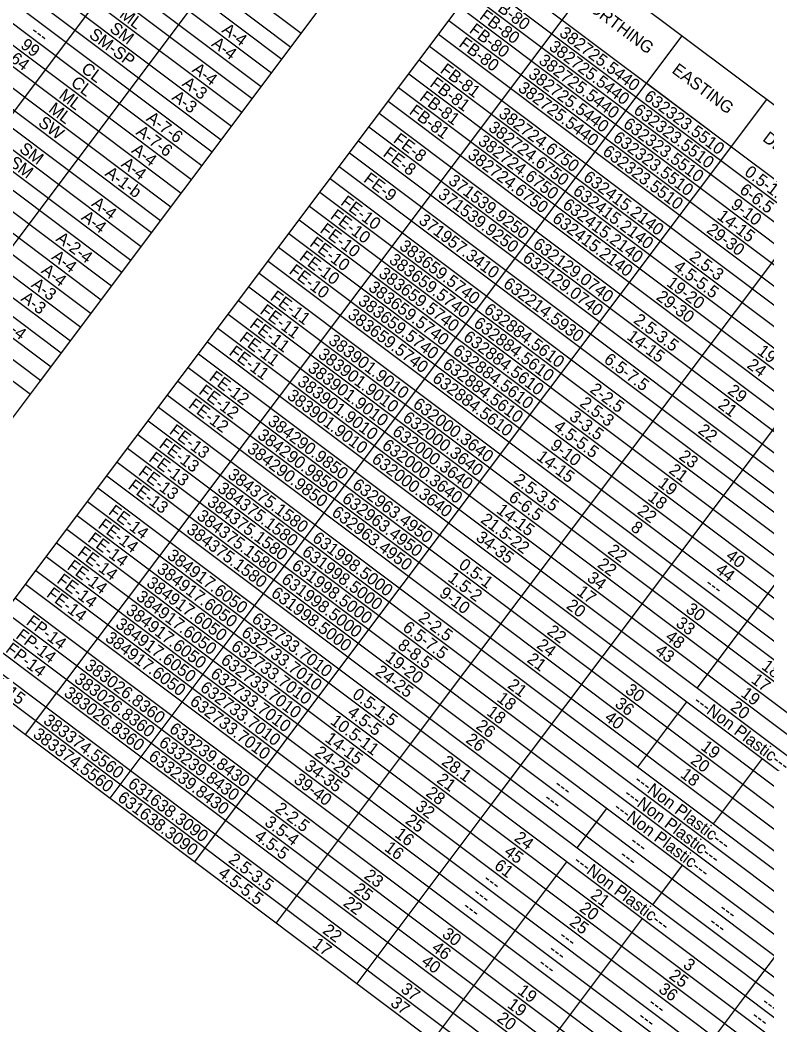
# Model space of a CAD drawing. Extents: x 627484.2 to 627514.4, y 367972.1 to 367996.9.
# Drawn here: x 627490.816 to 627494.205, y 367987.65 to 367992.209 of the extents above; entities that cross this region are included whole.
import ezdxf

# ---------------------------------------------------------------- set-up
doc = ezdxf.new("R2010")
doc.units = 0
doc.layers.add('Default', color=7, linetype='Continuous')
doc.layers.add('R_Survey Control', color=7, linetype='Continuous')

msp = doc.modelspace()

# ---------------------------------------------------------------- linework, layer by layer
at = {"layer": 'Default'}
for p, q in [((627486.8529, 367996.0833), (627492.0924, 367992.149)), ((627486.8061, 367996.021), (627492.0455, 367992.0866)), ((627486.7651, 367995.9664), (627492.0045, 367992.0321)), ((627486.7183, 367995.904), (627491.9577, 367991.9697)), ((627486.6715, 367995.8416), (627491.9109, 367991.9073)), ((627486.6305, 367995.7871), (627491.8699, 367991.8527)), ((627486.5836, 367995.7247), (627491.8231, 367991.7904)), ((627486.5368, 367995.6623), (627491.7762, 367991.728)), ((627486.49, 367995.5999), (627491.7294, 367991.6656)), ((627486.449, 367995.5454), (627491.6884, 367991.611)), ((627486.4021, 367995.483), (627491.6416, 367991.5487)), ((627486.3553, 367995.4206), (627491.5947, 367991.4863)), ((627486.3085, 367995.3583), (627491.5479, 367991.4239)), ((627486.2616, 367995.2959), (627491.5011, 367991.3616)), ((627486.2148, 367995.2335), (627491.4542, 367991.2992)), ((627486.1738, 367995.1789), (627491.4132, 367991.2446)), ((627486.127, 367995.1166), (627491.3664, 367991.1822)), ((627486.0801, 367995.0542), (627491.3196, 367991.1199)), ((627486.0392, 367994.9996), (627491.2786, 367991.0653)), ((627485.9923, 367994.9372), (627491.2317, 367991.0029)), ((627485.9455, 367994.8749), (627491.1849, 367990.9405)), ((627485.8987, 367994.8125), (627491.1381, 367990.8782)), ((627485.8518, 367994.7501), (627491.0912, 367990.8158)), ((627485.805, 367994.6877), (627491.0444, 367990.7534)), ((627485.764, 367994.6332), (627491.0034, 367990.6988)), ((627485.7172, 367994.5708), (627490.9566, 367990.6365)), ((627485.6703, 367994.5084), (627490.9097, 367990.5741)), ((627485.6235, 367994.4461), (627490.8629, 367990.5117)), ((627490.2002, 367991.0094), (627492.0473, 367993.4692)), ((627490.4887, 367990.7927), (627492.3241, 367993.237)), ((627490.9039, 367990.5663), (627492.71, 367992.9716)), ((627491.1222, 367990.0244), (627493.1098, 367992.6713)), ((627493.1098, 367992.6713), (627498.3493, 367988.737)), ((627492.9488, 367992.4569), (627498.1883, 367988.5226)), ((627491.4501, 367989.7782), (627493.4377, 367992.4251)), ((627492.902, 367992.3945), (627498.1414, 367988.4602)), ((627492.8552, 367992.3322), (627498.0946, 367988.3978)), ((627492.8083, 367992.2698), (627498.0477, 367988.3355)), ((627492.7615, 367992.2074), (627498.0009, 367988.2731)), ((627491.8339, 367989.49), (627493.8215, 367992.1369)), ((627492.7147, 367992.1451), (627497.9541, 367988.2107)), ((627492.6737, 367992.0905), (627497.9131, 367988.1562)), ((627492.6268, 367992.0281), (627497.8663, 367988.0938)), ((627492.58, 367991.9657), (627497.8194, 367988.0314)), ((627492.5332, 367991.9034), (627497.7726, 367987.969)), ((627492.2177, 367989.2017), (627494.2054, 367991.8487)), ((627492.4863, 367991.841), (627497.7257, 367987.9067)), ((627492.4453, 367991.7864), (627497.6848, 367987.8521)), ((627492.3985, 367991.724), (627497.6379, 367987.7897)), ((627492.3517, 367991.6617), (627497.5911, 367987.7273)), ((627492.3107, 367991.6071), (627497.5501, 367987.6728)), ((627492.5881, 367988.9237), (627494.5757, 367991.5706)), ((627492.2639, 367991.5447), (627497.5033, 367987.6104)), ((627492.2229, 367991.4901), (627497.4623, 367987.5558)), ((627492.176, 367991.4278), (627497.4155, 367987.4934)), ((627492.1292, 367991.3654), (627497.3686, 367987.4311)), ((627492.0824, 367991.303), (627497.3218, 367987.3687)), ((627492.9545, 367988.6485), (627494.9421, 367991.2954)), ((627492.0355, 367991.2406), (627497.2749, 367987.3063)), ((627491.9887, 367991.1783), (627497.2281, 367987.244)), ((627491.9419, 367991.1159), (627497.1813, 367987.1816)), ((627491.9009, 367991.0613), (627497.1403, 367987.127)), ((627491.854, 367990.999), (627497.0935, 367987.0646)), ((627491.8072, 367990.9366), (627497.0466, 367987.0023)), ((627491.7604, 367990.8742), (627496.9998, 367986.9399)), ((627491.7135, 367990.8118), (627496.9529, 367986.8775)), ((627491.6667, 367990.7495), (627496.9061, 367986.8151)), ((627491.6257, 367990.6949), (627496.8651, 367986.7606)), ((627491.5789, 367990.6325), (627496.8183, 367986.6982)), ((627491.532, 367990.5701), (627496.7715, 367986.6358)), ((627489.4403, 367988.6172), (627490.9039, 367990.5663)), ((627491.4852, 367990.5078), (627496.7246, 367986.5734)), ((627491.4442, 367990.4532), (627496.6836, 367986.5189)), ((627491.3974, 367990.3908), (627496.6368, 367986.4565)), ((627494.1084, 367987.782), (627496.096, 367990.429)), ((627491.3506, 367990.3284), (627496.59, 367986.3941)), ((627491.3037, 367990.2661), (627496.5431, 367986.3317)), ((627491.2569, 367990.2037), (627496.4963, 367986.2694)), ((627491.21, 367990.1413), (627496.4495, 367986.207)), ((627491.1691, 367990.0868), (627496.4085, 367986.1524)), ((627490.5134, 367989.2135), (627491.1222, 367990.0244)), ((627491.1222, 367990.0244), (627496.3616, 367986.0901)), ((627491.0754, 367989.962), (627496.3148, 367986.0277)), ((627491.0286, 367989.8996), (627496.268, 367985.9653)), ((627490.9817, 367989.8373), (627496.2211, 367985.9029)), ((627490.8412, 367988.9673), (627491.4501, 367989.7782)), ((627490.9349, 367989.7749), (627496.1743, 367985.8406)), ((627490.888, 367989.7125), (627496.1275, 367985.7782)), ((627493.8889, 367989.1783), (627494.2577, 367989.6695)), ((627490.8412, 367989.6501), (627496.0806, 367985.7158)), ((627490.7944, 367989.5878), (627496.0338, 367985.6534)), ((627490.7475, 367989.5254), (627495.9869, 367985.5911)), ((627491.225, 367988.6791), (627491.8339, 367989.49)), ((627490.7007, 367989.463), (627495.9401, 367985.5287)), ((627490.6539, 367989.4007), (627495.8933, 367985.4663)), ((627490.607, 367989.3383), (627495.8464, 367985.404)), ((627490.5602, 367989.2759), (627495.7996, 367985.3416)), ((627490.5134, 367989.2135), (627495.7528, 367985.2792)), ((627491.6089, 367988.3909), (627492.2177, 367989.2017)), ((627493.6196, 367988.8197), (627493.842, 367989.116)), ((627491.9792, 367988.1128), (627492.5881, 367988.9237)), ((627493.9626, 367988.5621), (627494.1851, 367988.8584)), ((627492.3457, 367987.8376), (627492.9545, 367988.6485)), ((627493.3444, 367988.4533), (627493.4791, 367988.6326)), ((627492.6887, 367987.58), (627493.2976, 367988.3909)), ((627493.6875, 367988.1957), (627493.8221, 367988.375)), ((627493.0318, 367987.3224), (627493.6406, 367988.1333)), ((627493.4995, 367986.9712), (627494.1084, 367987.782))]:
    msp.add_line(p, q, dxfattribs=at)
at = {"layer": 'R_Survey Control'}
for p, q in [((627493.874, 367992.0975), (627493.874, 367992.0975)), ((627493.6605, 367991.9225), (627494.0444, 367991.6343))]:
    msp.add_line(p, q, dxfattribs=at)

# ---------------------------------------------------------------- texts
at = {"layer": 'Default'}
for s, p in [('FB-80', (627492.9441, 367992.2797)), ('NORTHING', (627493.3522, 367992.2873)), ('ML', (627491.2635, 367992.225)), ('FB-80', (627492.8973, 367992.2174)), ('---', (627490.861, 367992.1492)), ('SM-SP', (627491.1251, 367992.1338)), ('SM', (627491.2184, 367992.1612)), ('A-4', (627491.7281, 367992.1565)), ('FB-80', (627492.8505, 367992.155)), ('382725.5440', (627493.2593, 367992.1407)), ('99', (627490.8143, 367992.0867)), ('A-4', (627491.6813, 367992.0941)), ('FB-80', (627492.8036, 367992.0926)), ('382725.5440', (627493.2124, 367992.0783)), ('64', (627490.7672, 367992.0246)), ('382725.5440', (627493.1656, 367992.0159)), ('CL', (627491.0892, 367991.9778)), ('A-4', (627491.5934, 367991.9772)), ('FB-81', (627492.7186, 367991.9736)), ('382725.5440', (627493.1187, 367991.9535)), ('EASTING', (627493.7704, 367991.9733)), ('CL', (627491.0424, 367991.9155)), ('A-3', (627491.5482, 367991.9136)), ('FB-81', (627492.6718, 367991.9112)), ('ML', (627490.9883, 367991.8585)), ('382725.5440', (627493.0719, 367991.8912)), ('A-3', (627491.5014, 367991.8512)), ('FB-81', (627492.625, 367991.8488)), ('632323.5510', (627493.6431, 367991.8524)), ('ML', (627490.9415, 367991.7961)), ('FB-81', (627492.5781, 367991.7864)), ('382724.6750', (627492.9841, 367991.7742)), ('632323.5510', (627493.5963, 367991.7901)), ('SW', (627490.8942, 367991.7341)), ('A-7-6', (627491.385, 367991.7557)), ('632323.5510', (627493.5494, 367991.7277)), ('A-7-6', (627491.3382, 367991.6933)), ('382724.6750', (627492.9373, 367991.7118)), ('FE-8', (627492.5063, 367991.6575)), ('382724.6750', (627492.8904, 367991.6495)), ('632323.5510', (627493.5026, 367991.6653)), ('DEPTH', (627494.1821, 367991.6641)), ('SM', (627490.8086, 367991.6155)), ('A-4', (627491.3183, 367991.6107)), ('FE-8', (627492.4594, 367991.5951)), ('382724.6750', (627492.8436, 367991.5871)), ('632323.5510', (627493.4557, 367991.6029)), ('SM', (627490.7617, 367991.5531)), ('A-4', (627491.2714, 367991.5484)), ('A-1-b', (627491.1976, 367991.5063)), ('0.5-1.5', (627494.0997, 367991.5096)), ('FE-9', (627492.3711, 367991.4785)), ('371539.9250', (627492.7558, 367991.4702)), ('632415.2140', (627493.3679, 367991.486)), ('371539.9250', (627492.7089, 367991.4078)), ('632415.2140', (627493.3211, 367991.4236)), ('6-6.5', (627494.0772, 367991.4289)), ('A-4', (627491.1368, 367991.369)), ('FE-10', (627492.2668, 367991.374)), ('632415.2140', (627493.2743, 367991.3613)), ('9-10', (627494.0375, 367991.3612)), ('FE-10', (627492.22, 367991.3116)), ('14-15', (627493.9754, 367991.3103)), ('A-4', (627491.09, 367991.3067)), ('371957.3410', (627492.6211, 367991.2908)), ('632415.2140', (627493.2274, 367991.2989)), ('FE-10', (627492.1732, 367991.2492)), ('29-30', (627493.9276, 367991.2486)), ('A-2-4', (627490.9751, 367991.21)), ('FE-10', (627492.1263, 367991.1869)), ('383659.5740', (627492.5333, 367991.1739)), ('632129.0740', (627493.1396, 367991.1819)), ('FE-10', (627492.0795, 367991.1245)), ('2.5-3', (627493.8495, 367991.1244)), ('A-4', (627490.9553, 367991.1273)), ('383659.5740', (627492.4865, 367991.1115)), ('632129.0740', (627493.0928, 367991.1196)), ('A-4', (627490.9085, 367991.065)), ('FE-10', (627492.0327, 367991.0621)), ('383659.5740', (627492.4396, 367991.0491)), ('4.5-5.5', (627493.7777, 367991.0807)), ('A-3', (627490.8632, 367991.0014)), ('632214.5930', (627493.0049, 367991.0026)), ('19-20', (627493.7461, 367991.0069)), ('FE-11', (627491.9477, 367990.943)), ('383659.5740', (627492.3928, 367990.9868)), ('29-30', (627493.6993, 367990.9446)), ('A-3', (627490.8164, 367990.939)), ('383659.5740', (627492.346, 367990.9244)), ('FE-11', (627491.9008, 367990.8807)), ('383659.5740', (627492.2991, 367990.862)), ('632884.5610', (627492.9171, 367990.8857)), ('A-4', (627490.727, 367990.8233)), ('FE-11', (627491.854, 367990.8183)), ('632884.5610', (627492.8703, 367990.8233)), ('2.5-3.5', (627493.5962, 367990.8391)), ('FE-11', (627491.8072, 367990.7559)), ('632884.5610', (627492.8235, 367990.7609)), ('14-15', (627493.5656, 367990.7645)), ('383901.9010', (627492.2113, 367990.7451)), ('FE-11', (627491.7603, 367990.6935)), ('383901.9010', (627492.1645, 367990.6827)), ('632884.5610', (627492.7766, 367990.6985)), ('19', (627494.158, 367990.6976)), ('632884.5610', (627492.7298, 367990.6362)), ('6.5-7.5', (627493.4616, 367990.6597)), ('24', (627494.1109, 367990.6354)), ('FE-12', (627491.6699, 367990.5786)), ('383901.9010', (627492.1176, 367990.6203)), ('383901.9010', (627492.0708, 367990.558)), ('632884.5610', (627492.6829, 367990.5738)), ('FE-12', (627491.623, 367990.5162)), ('383901.9010', (627492.024, 367990.4956)), ('2-2.5', (627493.3981, 367990.5245)), ('29', (627494.0234, 367990.5183)), ('FE-12', (627491.5762, 367990.4538)), ('632000.3640', (627492.5951, 367990.4568)), ('2.5-3', (627493.3518, 367990.4617)), ('21', (627493.9792, 367990.454)), ('632000.3640', (627492.5483, 367990.3945)), ('3-3.5', (627493.3044, 367990.3997)), ('384290.9850', (627491.9361, 367990.3786)), ('FE-13', (627491.4897, 367990.3359)), ('384290.9850', (627491.8893, 367990.3163)), ('632000.3640', (627492.5015, 367990.3321)), ('4.5-5.5', (627493.2332, 367990.3557)), ('22', (627493.8887, 367990.339)), ('FE-13', (627491.4429, 367990.2735)), ('632000.3640', (627492.4546, 367990.2697)), ('9-10', (627493.2179, 367990.2696)), ('FE-13', (627491.3961, 367990.2111)), ('384290.9850', (627491.8425, 367990.2539)), ('14-15', (627493.1558, 367990.2187)), ('23', (627493.8022, 367990.221)), ('632000.3640', (627492.4078, 367990.2074)), ('FE-13', (627491.3492, 367990.1487)), ('384375.1580', (627491.7546, 367990.1369)), ('21', (627493.7567, 367990.1577)), ('FE-13', (627491.3024, 367990.0864)), ('632963.4950', (627492.32, 367990.0904)), ('2.5-3.5', (627493.0517, 367990.114)), ('19', (627493.7072, 367990.0973)), ('384375.1580', (627491.7078, 367990.0746)), ('6-6.5', (627493.0293, 367990.0333)), ('18', (627493.6609, 367990.0345)), ('384375.1580', (627491.661, 367990.0122)), ('632963.4950', (627492.2731, 367990.028)), ('FE-14', (627491.213, 367989.9706)), ('384375.1580', (627491.6141, 367989.9498)), ('632963.4950', (627492.2263, 367989.9657)), ('14-15', (627492.9743, 367989.977)), ('22', (627493.6135, 367989.9725)), ('FE-14', (627491.1661, 367989.9082)), ('21.5-22', (627492.9023, 367989.9335)), ('8', (627493.5835, 367989.8976)), ('FE-14', (627491.1193, 367989.8459)), ('384375.1580', (627491.5673, 367989.8874)), ('631998.5000', (627492.1385, 367989.8487)), ('34-35', (627492.8806, 367989.8523)), ('FE-14', (627491.0725, 367989.7835)), ('384917.6050', (627491.4795, 367989.7705)), ('631998.5000', (627492.0916, 367989.7863)), ('22', (627493.4789, 367989.7932)), ('40', (627494.0149, 367989.7687)), ('FE-14', (627491.0256, 367989.7211)), ('631998.5000', (627492.0448, 367989.724)), ('0.5-1', (627492.8028, 367989.7278)), ('22', (627493.432, 367989.7309)), ('384917.6050', (627491.4326, 367989.7081)), ('34', (627493.385, 367989.6686)), ('44', (627493.9681, 367989.7063)), ('FE-14', (627490.9788, 367989.6587)), ('384917.6050', (627491.3858, 367989.6457)), ('631998.5000', (627491.998, 367989.6616)), ('1.5-2', (627492.7533, 367989.6675)), ('---', (627493.9214, 367989.6438)), ('FE-14', (627490.932, 367989.5964)), ('384917.6050', (627491.339, 367989.5834)), ('631998.5000', (627491.9511, 367989.5992)), ('9-10', (627492.7144, 367989.5991)), ('17', (627493.3385, 367989.606)), ('20', (627493.2913, 367989.5439)), ('384917.6050', (627491.2921, 367989.521)), ('2-2.5', (627492.6195, 367989.4875)), ('30', (627493.8334, 367989.527)), ('FP-14', (627490.8401, 367989.4703)), ('384917.6050', (627491.2453, 367989.4586)), ('632733.7010', (627491.8633, 367989.4823)), ('6.5-7.5', (627492.5483, 367989.4435)), ('33', (627493.7881, 367989.4635)), ('FP-14', (627490.7932, 367989.4079)), ('384917.6050', (627491.1985, 367989.3963)), ('632733.7010', (627491.8165, 367989.4199)), ('22', (627493.2037, 367989.4268)), ('48', (627493.7405, 367989.4017)), ('FP-14', (627490.7464, 367989.3455)), ('632733.7010', (627491.7696, 367989.3575)), ('8-8.5', (627492.5258, 367989.3628)), ('24', (627493.1567, 367989.3646)), ('19-20', (627492.4698, 367989.3073)), ('43', (627493.6945, 367989.3387)), ('383026.8360', (627491.1048, 367989.2715)), ('632733.7010', (627491.7228, 367989.2952)), ('21', (627493.1127, 367989.3001)), ('18', (627494.1772, 367989.2689)), ('FP-15', (627490.6537, 367989.22)), ('383026.8360', (627491.058, 367989.2091)), ('632733.7010', (627491.676, 367989.2328)), ('24-25', (627492.424, 367989.2442)), ('632733.7010', (627491.6291, 367989.1704)), ('21', (627493.0249, 367989.1831)), ('17', (627494.13, 367989.2068)), ('383026.8360', (627491.0111, 367989.1468)), ('0.5-1.5', (627492.3199, 367989.1394)), ('18', (627492.9759, 367989.1223)), ('30', (627493.5583, 367989.1605)), ('19', (627494.083, 367989.1445)), ('632733.7010', (627491.5823, 367989.108)), ('36', (627493.5115, 367989.0981)), ('---Non Plastic---', (627493.8685, 367989.1105)), ('20', (627494.036, 367989.0823)), ('4.5-5', (627492.2975, 367989.0587)), ('18', (627492.9291, 367989.06)), ('40', (627493.4646, 367989.0358)), ('383374.5560', (627490.9174, 367989.022)), ('633239.8430', (627491.4886, 367988.9833)), ('10.5-11', (627492.22, 367989.0194)), ('26', (627492.8816, 367988.998)), ('383374.5560', (627490.8706, 367988.9596)), ('14-15', (627492.1956, 367988.9401)), ('633239.8430', (627491.4418, 367988.9209)), ('26', (627492.8348, 367988.9357)), ('19', (627493.9016, 367988.9028)), ('633239.8430', (627491.3949, 367988.8585)), ('24-25', (627492.1488, 367988.8777)), ('34-35', (627492.102, 367988.8153)), ('28.1', (627492.7253, 367988.835)), ('20', (627493.8545, 367988.8406)), ('39-40', (627492.0542, 367988.7537)), ('21', (627492.7029, 367988.7543)), ('18', (627493.8084, 367988.7777)), ('631638.3090', (627491.3013, 367988.7338)), ('---', (627493.2364, 367988.7316)), ('---Non Plastic---', (627493.5992, 367988.7518)), ('631638.3090', (627491.2544, 367988.6714)), ('28', (627492.6539, 367988.6935)), ('---Non Plastic---', (627493.5524, 367988.6894)), ('2-2.5', (627491.9696, 367988.6221)), ('32', (627492.6066, 367988.6315)), ('---', (627493.1896, 367988.6692)), ('---Non Plastic---', (627493.5056, 367988.6271)), ('3.5-4', (627491.9217, 367988.5605)), ('25', (627492.5605, 367988.5686)), ('4.5-5', (627491.8759, 367988.4974)), ('16', (627492.5128, 367988.5069)), ('24', (627493.0547, 367988.4901)), ('16', (627492.4659, 367988.4445)), ('---', (627493.5795, 367988.474)), ('2.5-3.5', (627491.7579, 367988.3909)), ('45', (627493.0089, 367988.4269)), ('---', (627493.5326, 367988.4116)), ('61', (627492.9639, 367988.3632)), ('---Non Plastic---', (627493.3241, 367988.3854)), ('4.5-5.5', (627491.7111, 367988.3285)), ('23', (627492.3737, 367988.3187)), ('25', (627492.3263, 367988.2567)), ('---', (627492.9144, 367988.3028)), ('---', (627492.8676, 367988.2404)), ('21', (627493.4007, 367988.2303)), ('22', (627492.2787, 367988.1949)), ('20', (627493.351, 367988.1701)), ('---', (627492.8208, 367988.1781)), ('---', (627493.9849, 367988.1696)), ('22', (627492.185, 367988.0702)), ('25', (627493.3051, 367988.107)), ('---', (627493.9381, 367988.1072)), ('30', (627492.7269, 367988.0534)), ('---', (627493.2575, 367988.0452)), ('17', (627492.1383, 367988.0077)), ('46', (627492.6802, 367987.991)), ('---', (627493.2106, 367987.9828)), ('40', (627492.6333, 367987.9287)), ('---', (627493.1638, 367987.9205)), ('3', (627493.8211, 367987.9146)), ('25', (627493.7574, 367987.8649)), ('37', (627492.5399, 367987.8037)), ('36', (627493.7097, 367987.8032)), ('19', (627493.0702, 367987.7957)), ('37', (627492.493, 367987.7413)), ('19', (627493.0234, 367987.7333)), ('---', (627493.6629, 367987.7408)), ('---', (627494.1777, 367987.7444)), ('20', (627492.9763, 367987.6711)), ('---', (627493.6161, 367987.6784)), ('---', (627494.1309, 367987.682))]:
    msp.add_text(s, height=0.055, rotation=323.0968, dxfattribs=at).set_placement(p)

doc.saveas('drawing.dxf')
